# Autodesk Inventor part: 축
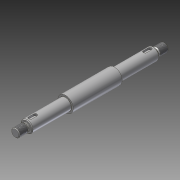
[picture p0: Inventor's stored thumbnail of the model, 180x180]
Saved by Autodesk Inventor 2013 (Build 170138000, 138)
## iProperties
Created: 2018-11
Part Number: 축
Material: 강철, 연강
Document SubType Name: Modeling
Designer: mduedu
Density: 1 g/cm^3
Author: mduedu
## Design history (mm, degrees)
sketch "스케치1"
  geometry: L1 (-35, 0)-(35, 0); L2 (35, 0)-(35, 11); L3 (35, 11)-(-35, 11); L4 (-35, 11)-(-35, 0); L5 (-35, 0)-(-91, 0); L6 (-91, 0)-(-91, 7.5); L7 (-91, 8.5)-(-90, 8.5); L8 (-35, 8.5)-(-35, 0); L9 (-91, 0)-(-107, 0); L10 (-107, 0)-(-107, 6); L11 (-107, 6)-(-94.732, 6); L12 (-91, 5)-(-91, 0); L13 (0, 0)-(0, 11); L14 (35, 0)-(91, 0); L15 (91, 0)-(91, 5); L16 (91, 8.5)-(90, 8.5); L17 (35, 8.5)-(35, 0); L18 (91, 0)-(107, 0); L19 (107, 0)-(107, 6); L20 (107, 6)-(94.732, 6); L21 (-91, 7.5)-(-90, 8.5); L22 (-90, 8.5)-(-35, 8.5); L23 (-91, 7.5)-(-91, 8.5); L24 (91, 7.5)-(90, 8.5); L25 (91, 7.5)-(91, 8.5); L26 (90, 8.5)-(35, 8.5); L27 (91, 5)-(91, 7.5); L28 (-94.732, 6)-(-93, 5); L29 (-93, 5)-(-91, 5); L30 (94.732, 6)-(93, 5); L31 (93, 5)-(91, 5); 1 further point
  constraints: 62 end point, 8 parallel, 8 symmetric about line, 5 perpendicular, 3 horizontal, 2 collinear, 2 midpoint, 2 vertical, 1 coincident
  dimensions: "d0" = 22 diameter of L3 L1; "d2" = 17 diameter of L7 L5; "d3" = 12 diameter of L11 L9; "d4" = 70 distance of L2.end L3.end; "d5" = 56 distance of L7.start L8.start; "d6" = 214 distance between parallel lines of L19 L10; "d26" = 45 deg angle of L22 L21; "d30" = 45 deg angle of L16 L24 (= d26); "d32" = 30 deg angle of L11 L28; "d33" = 10 diameter of L29 L9 (computed from d3); "d34" = 2 distance of L12.start L28.end; "d37" = 1 horizontal distance of L6.end L7.end
revolve "회전1" sketch "스케치1" stored, may be unused: angle "d7" = 90 deg
fillet "모깎기1" dims "d8" = 0.3
node "작업 평면1"
sketch "스케치2" dims "d11" = 12
  geometry: L1 (78.5, 2.5)-(85.5, 2.5); L2 (85.5, 2.5)-(85.5, -2.5); L3 (85.5, -2.5)-(78.5, -2.5); L4 (78.5, -2.5)-(78.5, 2.5); L5 (91, 7.5)-(91, -7.5) reference; 3 further points
  constraints: 8 end point, 2 midpoint, 2 parallel, 2 vertical alignment, 1 horizontal, 1 horizontal alignment, 1 perpendicular, 4 other
  dimensions: "d10" = 5 distance between parallel lines of L3 L1; "d28" = 3 dimension on L5
extrude "돌출1" cut sketch "스케치2" distance "d12" = 3; taper "d13" = 0 deg
feature "스레드1" dims "d17" = 12, "d18" = 0
feature "스레드2" dims "d19" = 12, "d20" = 0
chamfer "모따기2" distance "d21" = 1; stored, may be unused: second distance "d22" = 2, angle "d23" = 45 deg
fillet "모깎기2" dims "d35" = 0.6
node "솔리드1"
mirror "대칭1"
other parameters: "d27" = 8.5
